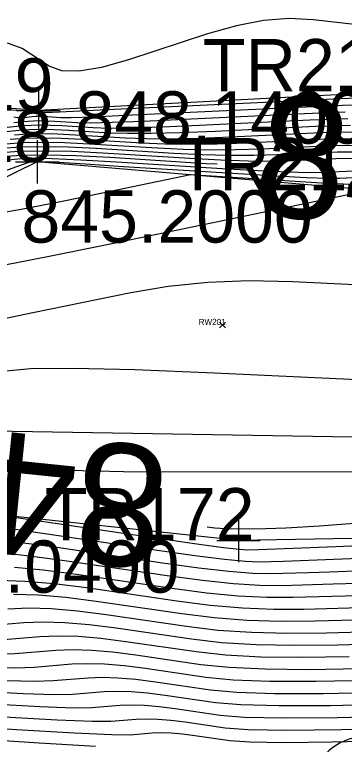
# Model space of a CAD drawing. Extents: x 1654928 to 1810050, y 486881 to 626330.
# Drawn here: x 1801330.33 to 1801337.91, y 489780.62 to 489797.37 of the extents above; entities that cross this region are included whole.
import ezdxf

# ---------------------------------------------------------------- set-up
doc = ezdxf.new("R2010")
doc.units = 0
for name, color, linetype in [('DR_X_Ditch', 7, 'Continuous'), ('DT_X_Contour_Major', 7, 'Continuous'), ('DT_X_Contour_Minor', 7, 'Continuous'), ('GK_Visualization', 7, 'Continuous'), ('SV_X_Shot_Marker', 7, 'Continuous'), ('SV_X_Text_Elevation', 7, 'Continuous'), ('SV_X_Text_Name', 7, 'Continuous'), ('SV_X_Toe_of_Slope', 7, 'Continuous'), ('SV_X_Top_of_Bank', 7, 'Continuous'), ('VG_X_Cells', 7, 'Continuous')]:
    doc.layers.add(name, color=color, linetype=linetype)

msp = doc.modelspace()

# ---------------------------------------------------------------- linework, layer by layer
at = {"layer": 'DR_X_Ditch'}
msp.add_lwpolyline([(1801415.613, 489805.461), (1801399.12, 489798.656), (1801394.115, 489798.231), (1801381.169, 489793.34), (1801378.227, 489791.154), (1801376.864, 489788.486), (1801373.817, 489786.687), (1801350.547, 489785.463), (1801345.905, 489787.547), (1801327.981, 489787.847), (1801322.506, 489787.279)], dxfattribs=at)
at = {"layer": 'DT_X_Contour_Major'}
for points in [[(1801338.583, 489795.469), (1801337.806, 489795.438), (1801336.74, 489795.389), (1801332.449, 489795.186), (1801331.681, 489795.151), (1801331.207, 489795.13), (1801331.028, 489795.125), (1801330.943, 489795.13), (1801330.885, 489795.132), (1801330.86, 489795.132), (1801330.839, 489795.13), (1801330.786, 489795.125), (1801330.765, 489795.124), (1801330.719, 489795.128), (1801330.694, 489795.133), (1801330.624, 489795.15), (1801330.382, 489795.17), (1801329.709, 489795.218), (1801327.071, 489795.4), (1801322.404, 489795.716), (1801320.867, 489795.818), (1801319.759, 489795.885)], [(1801338.11, 489794.677), (1801337.372, 489794.658), (1801335.298, 489794.559), (1801334.563, 489794.53), (1801333.915, 489794.517), (1801333.354, 489794.52), (1801332.88, 489794.539), (1801331.731, 489794.611), (1801331.32, 489794.631), (1801330.95, 489794.638), (1801330.621, 489794.631), (1801330.332, 489794.611)], [(1801334.984, 489793.939), (1801334.732, 489793.953), (1801332.519, 489794.092), (1801331.74, 489794.132), (1801331.065, 489794.149), (1801330.492, 489794.142), (1801330.021, 489794.112)], [(1801329.981, 489790.376), (1801330.756, 489790.533), (1801333, 489790.996), (1801333.863, 489791.142), (1801334.77, 489791.233), (1801335.722, 489791.268), (1801336.718, 489791.247), (1801339.433, 489791.119)], [(1801338.431, 489785.714), (1801337.34, 489785.634), (1801336.565, 489785.585), (1801336.107, 489785.569), (1801335.309, 489785.567), (1801334.931, 489785.589), (1801334.754, 489785.611)], [(1801330.33, 489784.695), (1801330.99, 489784.631), (1801331.758, 489784.53), (1801333.95, 489784.209), (1801334.74, 489784.106), (1801335.466, 489784.036), (1801336.126, 489784.001), (1801336.723, 489784), (1801338.226, 489784.042)], [(1801329.898, 489783.019), (1801330.916, 489783.103), (1801331.326, 489783.119), (1801331.792, 489783.106), (1801332.313, 489783.062), (1801332.89, 489782.988), (1801334.504, 489782.752), (1801335.178, 489782.678), (1801335.988, 489782.635), (1801336.934, 489782.622), (1801338.017, 489782.639)], [(1801319.737, 489782.096), (1801320.296, 489782.128), (1801320.683, 489782.126), (1801321.427, 489782.092), (1801322.528, 489782.029), (1801323.984, 489781.935), (1801328.343, 489781.644), (1801329.804, 489781.551), (1801330.918, 489781.491), (1801331.684, 489781.463), (1801332.103, 489781.467), (1801332.756, 489781.52), (1801333.019, 489781.531), (1801333.318, 489781.522), (1801333.652, 489781.494), (1801334.023, 489781.447), (1801335.058, 489781.295), (1801335.615, 489781.251), (1801336.51, 489781.234), (1801337.742, 489781.243), (1801339.312, 489781.279)]]:
    msp.add_lwpolyline(points, dxfattribs=at)
at = {"layer": 'DT_X_Contour_Minor'}
for points in [[(1801338.617, 489797.09), (1801337.195, 489797.256), (1801336.644, 489797.283), (1801336.055, 489797.237), (1801335.43, 489797.12), (1801334.768, 489796.932), (1801332.954, 489796.334), (1801332.329, 489796.157), (1801331.817, 489796.074), (1801331.417, 489796.085), (1801331.129, 489796.191), (1801330.51, 489796.598), (1801330.194, 489796.709), (1801329.71, 489796.736), (1801329.06, 489796.678), (1801328.241, 489796.537), (1801324.032, 489795.682), (1801320.172, 489795.944), (1801319.447, 489795.993)], [(1801338.62, 489795.307), (1801337.867, 489795.286), (1801336.866, 489795.243), (1801333.869, 489795.101), (1801332.872, 489795.055), (1801332.128, 489795.024), (1801331.636, 489795.008), (1801331.398, 489795.008), (1801331.1, 489795.026), (1801330.994, 489795.032), (1801330.898, 489795.033), (1801330.812, 489795.032), (1801330.738, 489795.026), (1801330.552, 489795.008), (1801330.48, 489795.004), (1801330.402, 489795.008), (1801330.318, 489795.019)], [(1801337.928, 489795.133), (1801336.993, 489795.097), (1801334.226, 489794.965), (1801333.295, 489794.924), (1801332.574, 489794.897), (1801332.066, 489794.886), (1801331.768, 489794.89), (1801331.258, 489794.922), (1801331.075, 489794.931), (1801330.911, 489794.934), (1801330.765, 489794.931), (1801330.636, 489794.922), (1801330.318, 489794.891)], [(1801337.988, 489794.981), (1801337.119, 489794.95), (1801334.583, 489794.83), (1801333.717, 489794.792), (1801333.021, 489794.771), (1801332.495, 489794.764), (1801332.139, 489794.773), (1801331.415, 489794.819), (1801331.157, 489794.831), (1801330.924, 489794.836), (1801330.717, 489794.831), (1801330.535, 489794.819), (1801330.085, 489794.774)], [(1801338.049, 489794.829), (1801337.246, 489794.804), (1801334.94, 489794.695), (1801334.14, 489794.661), (1801333.468, 489794.644), (1801332.924, 489794.642), (1801332.509, 489794.656), (1801331.573, 489794.715), (1801331.239, 489794.731), (1801330.937, 489794.737), (1801330.669, 489794.731), (1801330.434, 489794.715), (1801329.851, 489794.656)], [(1801338.232, 489794.372), (1801337.625, 489794.365), (1801336.012, 489794.289), (1801335.408, 489794.268), (1801334.809, 489794.264), (1801334.213, 489794.276), (1801333.62, 489794.305), (1801332.046, 489794.403), (1801331.483, 489794.431), (1801330.976, 489794.44), (1801330.525, 489794.431), (1801330.13, 489794.404)], [(1801338.171, 489794.524), (1801337.499, 489794.512), (1801335.655, 489794.424), (1801334.986, 489794.399), (1801334.362, 489794.391), (1801333.783, 489794.398), (1801333.25, 489794.422), (1801331.888, 489794.507), (1801331.402, 489794.531), (1801330.963, 489794.539), (1801330.573, 489794.531), (1801330.231, 489794.507)], [(1801338.293, 489794.22), (1801337.752, 489794.219), (1801336.369, 489794.153), (1801335.831, 489794.137), (1801335.256, 489794.137), (1801334.642, 489794.154), (1801333.991, 489794.188), (1801332.204, 489794.3), (1801331.565, 489794.331), (1801330.99, 489794.342), (1801330.477, 489794.331), (1801330.028, 489794.3)], [(1801338.353, 489794.067), (1801337.879, 489794.073), (1801336.726, 489794.018), (1801336.254, 489794.006), (1801335.702, 489794.011), (1801335.072, 489794.032), (1801334.361, 489794.071), (1801332.361, 489794.196), (1801331.647, 489794.231), (1801331.003, 489794.243), (1801330.429, 489794.231), (1801329.927, 489794.196)], [(1801338.132, 489793.78), (1801337.44, 489793.747), (1801337.099, 489793.744), (1801336.596, 489793.757), (1801335.93, 489793.788), (1801335.102, 489793.836), (1801332.676, 489793.988), (1801331.853, 489794.035), (1801331.2, 489794.062), (1801330.719, 489794.07), (1801330.409, 489794.057), (1801329.812, 489793.997)], [(1801338.258, 489793.634), (1801337.797, 489793.612), (1801337.522, 489793.612), (1801337.043, 489793.63), (1801336.36, 489793.666), (1801335.472, 489793.719), (1801332.834, 489793.884), (1801331.965, 489793.938), (1801331.335, 489793.976), (1801330.946, 489793.997), (1801330.797, 489794.002), (1801330.719, 489793.994), (1801330.618, 489793.964), (1801330.375, 489793.88), (1801329.989, 489793.742)], [(1801338.011, 489793.477), (1801337.754, 489793.487), (1801337.383, 489793.507), (1801334.373, 489793.694), (1801331.539, 489793.109), (1801330.961, 489792.993), (1801330.443, 489792.896), (1801329.984, 489792.818)], [(1801338.511, 489793.341), (1801332.343, 489792.068), (1801331.124, 489791.821), (1801330.112, 489791.625)], [(1801308.213, 489793.138), (1801315.69, 489784.771), (1801317.125, 489783.189), (1801318.224, 489782.03), (1801318.987, 489781.294), (1801319.414, 489780.98), (1801320.106, 489780.708), (1801320.32, 489780.635), (1801320.443, 489780.62), (1801320.476, 489780.665), (1801320.419, 489780.768), (1801319.938, 489781.386), (1801329.152, 489780.771), (1801330.899, 489780.658), (1801332.194, 489780.581)], [(1801330.132, 489789.197), (1801330.702, 489789.25), (1801331.69, 489789.26), (1801333.098, 489789.228), (1801334.925, 489789.154), (1801340.354, 489788.898)], [(1801319.737, 489787.393), (1801320.412, 489785.348), (1801320.751, 489784.684), (1801321.259, 489784.226), (1801321.939, 489783.972), (1801322.788, 489783.925), (1801327.151, 489784.181), (1801329.444, 489784.369), (1801329.971, 489784.39), (1801330.571, 489784.373), (1801331.242, 489784.317), (1801331.984, 489784.222), (1801334.061, 489783.918), (1801334.828, 489783.82), (1801335.57, 489783.756), (1801336.288, 489783.725), (1801336.981, 489783.728), (1801338.798, 489783.779)], [(1801339.247, 489786.882), (1801334.457, 489786.875), (1801332.836, 489786.882), (1801331.565, 489786.909), (1801330.643, 489786.955), (1801330.072, 489787.02), (1801329.014, 489787.221), (1801328.594, 489787.278), (1801328.126, 489787.3), (1801327.612, 489787.286), (1801327.05, 489787.236), (1801325.49, 489787.055), (1801324.94, 489786.985), (1801324.46, 489786.911), (1801324.049, 489786.834), (1801323.708, 489786.752), (1801322.893, 489786.53)], [(1801328.291, 489785.99), (1801328.534, 489786.053), (1801328.615, 489786.071), (1801328.669, 489786.08), (1801328.778, 489786.093), (1801328.834, 489786.093), (1801328.921, 489786.084), (1801329.038, 489786.067), (1801329.185, 489786.04), (1801329.945, 489785.896), (1801333.833, 489785.327), (1801334.573, 489785.221), (1801335.129, 489785.145), (1801335.5, 489785.101), (1801335.687, 489785.088), (1801335.937, 489785.095), (1801337.714, 489785.165), (1801338.971, 489785.216)], [(1801330.234, 489785.576), (1801331.078, 489785.455), (1801333.618, 489785.083), (1801334.478, 489784.962), (1801335.152, 489784.877), (1801335.642, 489784.828), (1801335.946, 489784.816), (1801336.509, 489784.832), (1801337.667, 489784.875), (1801344.779, 489785.161)], [(1801329.848, 489785.339), (1801330.486, 489785.261), (1801331.305, 489785.147), (1801333.729, 489784.792), (1801334.565, 489784.676), (1801335.257, 489784.597), (1801335.803, 489784.553), (1801336.205, 489784.544), (1801337.082, 489784.569), (1801337.565, 489784.585), (1801338.355, 489784.614)], [(1801330.089, 489785.017), (1801330.738, 489784.946), (1801331.531, 489784.838), (1801333.84, 489784.5), (1801334.653, 489784.391), (1801335.361, 489784.317), (1801335.965, 489784.277), (1801336.464, 489784.272), (1801337.654, 489784.305), (1801338.224, 489784.323)], [(1801330.31, 489784.073), (1801330.876, 489784.056), (1801331.509, 489784.003), (1801332.211, 489783.913), (1801334.172, 489783.626), (1801334.915, 489783.535), (1801335.675, 489783.476), (1801336.45, 489783.449), (1801337.24, 489783.456), (1801339.371, 489783.515)], [(1801330.18, 489783.736), (1801330.649, 489783.755), (1801331.181, 489783.739), (1801331.777, 489783.689), (1801332.437, 489783.605), (1801334.283, 489783.335), (1801335.003, 489783.249), (1801335.779, 489783.196), (1801336.611, 489783.174), (1801337.499, 489783.183), (1801339.943, 489783.252)], [(1801329.457, 489783.33), (1801330.548, 489783.42), (1801330.987, 489783.437), (1801331.486, 489783.422), (1801332.045, 489783.376), (1801332.664, 489783.297), (1801334.394, 489783.043), (1801335.09, 489782.964), (1801335.883, 489782.915), (1801336.773, 489782.898), (1801337.758, 489782.911), (1801341.523, 489783.018)], [(1801319.77, 489783.072), (1801320.016, 489782.85), (1801320.344, 489782.728), (1801320.754, 489782.705), (1801321.957, 489782.776), (1801322.489, 489782.79), (1801323.179, 489782.779), (1801324.03, 489782.744), (1801325.04, 489782.684), (1801327.946, 489782.49), (1801328.94, 489782.43), (1801329.744, 489782.394), (1801330.357, 489782.384), (1801330.78, 489782.398), (1801331.652, 489782.47), (1801332.003, 489782.484), (1801332.402, 489782.472), (1801332.849, 489782.435), (1801333.343, 489782.372), (1801334.726, 489782.169), (1801335.353, 489782.108), (1801336.197, 489782.075), (1801337.258, 489782.071), (1801338.535, 489782.095)], [(1801329.915, 489782.691), (1801330.339, 489782.709), (1801331.284, 489782.786), (1801331.665, 489782.802), (1801332.097, 489782.789), (1801332.581, 489782.748), (1801333.117, 489782.68), (1801334.615, 489782.461), (1801335.265, 489782.393), (1801336.092, 489782.355), (1801337.096, 489782.346), (1801338.276, 489782.367)], [(1801319.809, 489782.621), (1801320.078, 489782.521), (1801320.415, 489782.502), (1801321.403, 489782.56), (1801321.887, 489782.569), (1801322.595, 489782.55), (1801323.529, 489782.506), (1801324.688, 489782.434), (1801328.078, 489782.208), (1801329.228, 489782.137), (1801330.136, 489782.093), (1801330.8, 489782.077), (1801331.221, 489782.088), (1801332.02, 489782.153), (1801332.342, 489782.166), (1801332.707, 489782.155), (1801333.117, 489782.121), (1801333.57, 489782.063), (1801334.837, 489781.878), (1801335.44, 489781.822), (1801336.301, 489781.794), (1801337.419, 489781.795), (1801338.794, 489781.823)], [(1801319.812, 489782.314), (1801320.076, 489782.299), (1801320.85, 489782.344), (1801321.285, 489782.347), (1801322.011, 489782.321), (1801323.028, 489782.267), (1801324.336, 489782.185), (1801328.211, 489781.926), (1801329.516, 489781.844), (1801330.527, 489781.792), (1801331.242, 489781.77), (1801331.662, 489781.777), (1801332.388, 489781.837), (1801332.68, 489781.848), (1801333.013, 489781.839), (1801333.385, 489781.807), (1801333.796, 489781.755), (1801334.948, 489781.586), (1801335.528, 489781.537), (1801336.406, 489781.514), (1801337.581, 489781.519), (1801339.053, 489781.551)], [(1801319.742, 489781.912), (1801320.081, 489781.904), (1801320.843, 489781.863), (1801322.027, 489781.79), (1801323.632, 489781.685), (1801328.476, 489781.362), (1801330.092, 489781.259), (1801331.309, 489781.19), (1801332.126, 489781.155), (1801332.544, 489781.156), (1801333.124, 489781.204), (1801333.358, 489781.213), (1801333.623, 489781.205), (1801333.92, 489781.18), (1801334.249, 489781.138), (1801335.169, 489781.004), (1801335.696, 489780.966), (1801336.589, 489780.953), (1801337.846, 489780.966), (1801339.468, 489781.004)], [(1801319.48, 489781.682), (1801320.259, 489781.634), (1801321.526, 489781.552), (1801328.608, 489781.081), (1801330.38, 489780.966), (1801331.701, 489780.889), (1801332.569, 489780.848), (1801332.985, 489780.845), (1801333.492, 489780.887), (1801333.696, 489780.895), (1801333.928, 489780.888), (1801334.188, 489780.867), (1801334.476, 489780.83), (1801335.28, 489780.712), (1801335.741, 489780.679), (1801336.521, 489780.668), (1801337.62, 489780.679), (1801339.038, 489780.712)]]:
    msp.add_lwpolyline(points, dxfattribs=at)
at = {"layer": 'GK_Visualization'}
for p, q in [((1801335.041, 489790.185), (1801335.175, 489790.318)), ((1801335.041, 489790.318), (1801335.175, 489790.185))]:
    msp.add_line(p, q, dxfattribs=at)
at = {"layer": 'SV_X_Shot_Marker'}
for p, q in [((1801330.88, 489795.672), (1801330.88, 489794.672)), ((1801330.38, 489795.172), (1801331.38, 489795.172)), ((1801330.88, 489795.172), (1801330.88, 489795.172)), ((1801330.855, 489794.494), (1801330.855, 489793.494)), ((1801330.355, 489793.994), (1801331.355, 489793.994)), ((1801330.855, 489793.994), (1801330.855, 489793.994)), ((1801335.479, 489785.806), (1801335.479, 489784.806)), ((1801334.979, 489785.306), (1801335.979, 489785.306)), ((1801335.479, 489785.306), (1801335.479, 489785.306))]:
    msp.add_line(p, q, dxfattribs=at)
at = {"layer": 'SV_X_Toe_of_Slope'}
for points in [[(1801412.543, 489809.732), (1801392.991, 489804.275), (1801388.448, 489803.512), (1801377.572, 489796.441), (1801374.044, 489792.616), (1801367.753, 489789.382), (1801359.258, 489788.44), (1801349.57, 489789.663), (1801346.148, 489791.559), (1801338.511, 489793.341), (1801330.855, 489793.994), (1801326.103, 489791.66), (1801319.382, 489791.876), (1801317.575, 489794.338), (1801316.785, 489794.599)], [(1801417.791, 489799.995), (1801412.832, 489796.754), (1801412.089, 489795.17), (1801401.953, 489790.438), (1801397.863, 489793.263), (1801395.881, 489794.687), (1801394.491, 489796.208), (1801381.141, 489790.72), (1801379.18, 489788.057), (1801375.237, 489785.681), (1801360.556, 489782.746), (1801350.439, 489783.352), (1801348.143, 489785.528), (1801335.479, 489785.306), (1801328.907, 489786.007), (1801321.924, 489784.909)]]:
    msp.add_lwpolyline(points, dxfattribs=at)
at = {"layer": 'SV_X_Top_of_Bank'}
msp.add_lwpolyline([(1801422.074, 489809.374), (1801419.071, 489811.095), (1801415.847, 489811.951), (1801411.348, 489810.567), (1801392.1, 489806.2), (1801386.944, 489805.19), (1801377.801, 489798.251), (1801372.871, 489798.042), (1801363.859, 489794.96), (1801356.721, 489793.409), (1801350.319, 489794.339), (1801339.193, 489795.613), (1801330.88, 489795.172), (1801318.326, 489796.108)], dxfattribs=at)
at = {"layer": 'VG_X_Cells'}
msp.add_arc((1801338.421, 489779.487), 1.317, 354.0047, 205.9741, dxfattribs=at)

# ---------------------------------------------------------------- texts
at = {"layer": 'DT_X_Contour_Major'}
for s, rotation, p in [('846', 352.5909, (1801335.736, 489792.842)), ('845', 174.1578, (1801333.942, 489787.41))]:
    msp.add_text(s, height=2.8, rotation=rotation, dxfattribs=at).set_placement(p)
at = {"layer": 'GK_Visualization'}
msp.add_text('RW201', height=0.14, dxfattribs=at).set_placement((1801334.561, 489790.251))
at = {"layer": 'SV_X_Text_Elevation'}
for s, p in [('848.1400', (1801331.73, 489794.413)), ('845.2000', (1801330.49, 489792.141)), ('845.0400', (1801327.43, 489784.106))]:
    msp.add_text(s, height=1.2, dxfattribs=at).set_placement(p)
at = {"layer": 'SV_X_Text_Name'}
for s, p in [('TR216', (1801334.659, 489795.613)), ('TR219', (1801326.411, 489795.172)), ('TR218', (1801326.387, 489793.994)), ('TR217', (1801334.052, 489793.341)), ('TR172', (1801331.03, 489785.306))]:
    msp.add_text(s, height=1.2, dxfattribs=at).set_placement(p)

doc.saveas('drawing.dxf')
